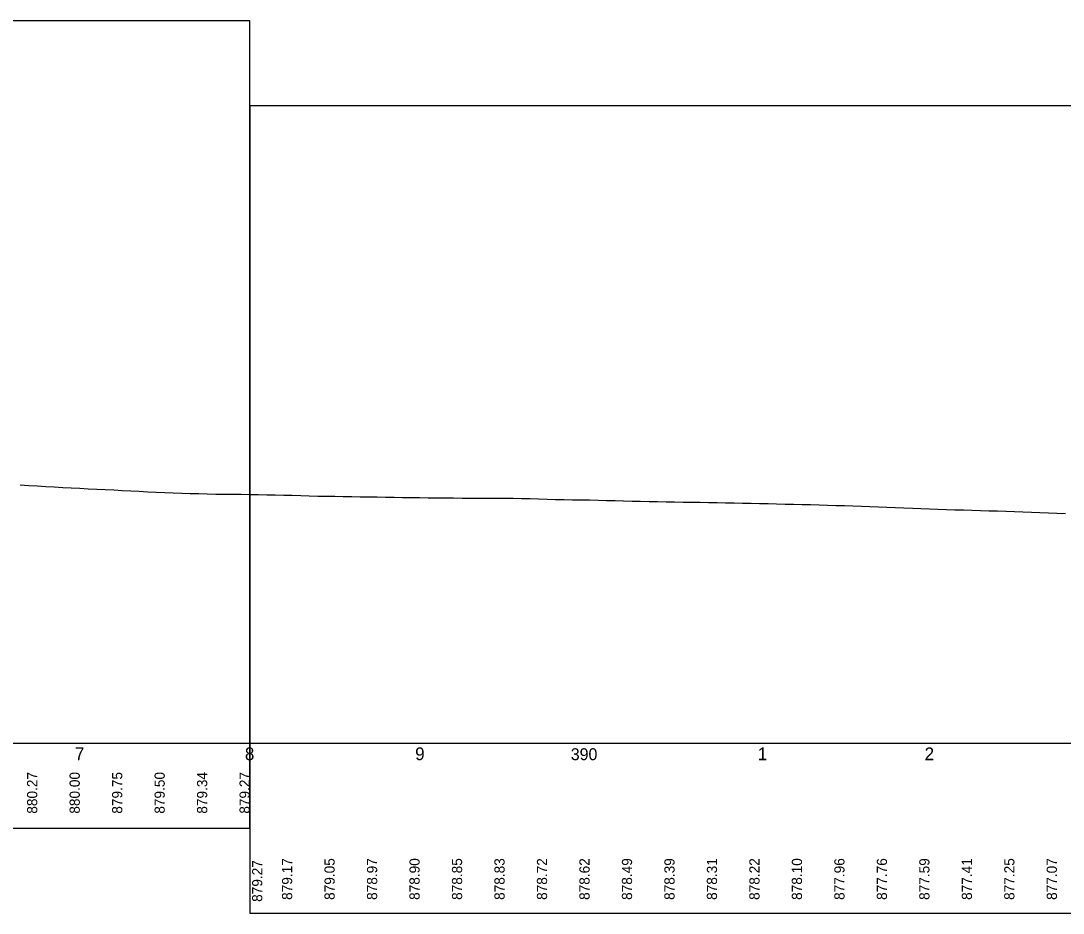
# Model space of a CAD drawing. Extents: x 4180 to 16997695, y 4 to 12629821.
# Drawn here: x 16991085 to 16991699, y 12626688 to 12627213 of the extents above; entities that cross this region are included whole.
import ezdxf

# ---------------------------------------------------------------- set-up
doc = ezdxf.new("R2010")
doc.units = 0
for name, color, linetype in [('Default', 7, 'Continuous'), ('RD_DDB_Profile_EX', 7, 'Continuous'), ('RD_DDB_StaTX', 7, 'Continuous'), ('RD_DDB_StripGrade', 7, 'Continuous'), ('RD_GPK_Profile_Cell', 7, 'Continuous')]:
    doc.layers.add(name, color=color, linetype=linetype)

msp = doc.modelspace()

# ---------------------------------------------------------------- linework, layer by layer
at = {"layer": 'Default'}
for points in [[(16989719.88, 12626737.79), (16991219.88, 12626737.79), (16991219.88, 12627212.79), (16989719.88, 12627212.79)], [(16991219.88, 12626687.79), (16992719.88, 12626687.79), (16992719.88, 12627162.79), (16991219.88, 12627162.79)]]:
    msp.add_lwpolyline(points, close=True, dxfattribs=at)
at = {"layer": 'RD_DDB_Profile_EX'}
for points in [[(16991084.88, 12626939.73), (16991089.88, 12626939.43), (16991094.88, 12626939.13), (16991099.88, 12626938.85), (16991104.88, 12626938.56), (16991109.88, 12626938.28), (16991114.88, 12626938.01), (16991119.88, 12626937.77)], [(16991119.88, 12626937.77), (16991124.88, 12626937.53), (16991129.88, 12626937.27), (16991134.88, 12626937.03), (16991139.88, 12626936.78), (16991144.88, 12626936.53), (16991149.88, 12626936.28), (16991154.88, 12626936.02), (16991159.88, 12626935.74), (16991164.88, 12626935.49), (16991169.88, 12626935.3), (16991174.88, 12626935.11), (16991179.88, 12626934.92), (16991184.88, 12626934.77), (16991189.88, 12626934.63), (16991194.88, 12626934.49), (16991199.88, 12626934.35), (16991204.88, 12626934.28), (16991209.88, 12626934.24), (16991214.88, 12626934.21), (16991219.88, 12626934.16), (16991224.88, 12626934.06), (16991229.88, 12626933.96), (16991234.88, 12626933.86), (16991239.88, 12626933.76), (16991244.88, 12626933.62), (16991249.88, 12626933.47), (16991254.88, 12626933.31), (16991259.88, 12626933.18), (16991264.88, 12626933.11), (16991269.88, 12626933.03), (16991274.88, 12626932.96), (16991279.88, 12626932.88), (16991284.88, 12626932.8), (16991289.88, 12626932.72), (16991294.88, 12626932.64), (16991299.88, 12626932.57), (16991304.88, 12626932.5), (16991309.88, 12626932.42), (16991314.88, 12626932.35), (16991319.88, 12626932.27), (16991324.88, 12626932.18), (16991329.88, 12626932.14), (16991334.88, 12626932.11), (16991339.88, 12626932.07), (16991344.88, 12626932.04), (16991349.88, 12626932.02), (16991354.88, 12626932.02), (16991359.88, 12626932.02), (16991364.88, 12626932.01), (16991369.88, 12626931.96), (16991374.88, 12626931.88), (16991379.88, 12626931.8), (16991384.88, 12626931.72), (16991389.88, 12626931.58), (16991394.88, 12626931.4), (16991399.88, 12626931.21), (16991404.88, 12626931.1), (16991409.88, 12626931.04), (16991414.88, 12626930.97), (16991419.88, 12626930.89), (16991424.88, 12626930.77), (16991429.88, 12626930.64), (16991434.88, 12626930.53), (16991439.88, 12626930.39), (16991444.88, 12626930.25), (16991449.88, 12626930.11), (16991454.88, 12626930), (16991459.88, 12626929.9), (16991464.88, 12626929.8), (16991469.88, 12626929.74), (16991474.88, 12626929.68), (16991479.88, 12626929.6), (16991484.88, 12626929.52), (16991489.88, 12626929.44), (16991494.88, 12626929.35), (16991499.88, 12626929.26), (16991504.88, 12626929.17), (16991509.88, 12626929.07), (16991514.88, 12626928.97), (16991519.88, 12626928.87), (16991524.88, 12626928.76), (16991529.88, 12626928.64), (16991534.88, 12626928.51), (16991539.88, 12626928.4), (16991544.88, 12626928.28), (16991549.88, 12626928.15), (16991554.88, 12626928.03), (16991559.88, 12626927.88), (16991564.88, 12626927.73), (16991569.88, 12626927.57), (16991574.88, 12626927.42), (16991579.88, 12626927.25), (16991584.88, 12626927.03), (16991589.88, 12626926.82), (16991594.88, 12626926.61), (16991599.88, 12626926.39), (16991604.88, 12626926.22), (16991609.88, 12626926.06), (16991614.88, 12626925.9), (16991619.88, 12626925.72)], [(16991619.88, 12626925.72), (16991624.88, 12626925.54), (16991629.88, 12626925.36), (16991634.88, 12626925.18), (16991639.88, 12626925.01), (16991644.88, 12626924.86), (16991649.88, 12626924.72), (16991654.88, 12626924.58), (16991659.88, 12626924.42), (16991664.88, 12626924.22), (16991669.88, 12626924.03), (16991674.88, 12626923.84), (16991679.88, 12626923.64), (16991684.88, 12626923.46), (16991689.88, 12626923.3), (16991694.88, 12626923.13), (16991699.88, 12626922.96)]]:
    msp.add_lwpolyline(points, dxfattribs=at)
at = {"layer": 'RD_GPK_Profile_Cell'}
msp.add_line((16972619.88, 12626787.79), (16997196.51, 12626787.79), dxfattribs=at)

# ---------------------------------------------------------------- texts
at = {"layer": 'RD_DDB_StaTX'}
for s, height, p in [('7', 7.5, (16991117, 12626777.79)), ('8', 7.5, (16991217.03, 12626777.79)), ('9', 7.5, (16991317.23, 12626777.79)), ('390', 7, (16991408.83, 12626777.79)), ('1', 7.5, (16991518.87, 12626777.79)), ('2', 7.5, (16991617.03, 12626777.79))]:
    msp.add_text(s, height=height, dxfattribs=at).set_placement(p)
at = {"layer": 'RD_DDB_StripGrade'}
for s, p in [('880.27', (16991094.88, 12626746.3)), ('880.00', (16991119.88, 12626746.3)), ('879.75', (16991144.88, 12626746.3)), ('879.50', (16991169.88, 12626746.3)), ('879.34', (16991194.88, 12626746.3)), ('879.27', (16991219.88, 12626746.3)), ('879.27', (16991227.28, 12626694.43)), ('879.17', (16991244.88, 12626695.58)), ('879.05', (16991269.88, 12626695.58)), ('878.97', (16991294.88, 12626695.58)), ('878.90', (16991319.88, 12626695.58)), ('878.85', (16991344.88, 12626695.58)), ('878.83', (16991369.88, 12626695.58)), ('878.72', (16991394.88, 12626695.58)), ('878.62', (16991419.88, 12626695.58)), ('878.49', (16991444.88, 12626695.58)), ('878.39', (16991469.88, 12626695.58)), ('878.31', (16991494.88, 12626695.58)), ('878.22', (16991519.88, 12626695.58)), ('878.10', (16991544.88, 12626695.58)), ('877.96', (16991569.88, 12626695.58)), ('877.76', (16991594.88, 12626695.58)), ('877.59', (16991619.88, 12626695.58)), ('877.41', (16991644.88, 12626695.58)), ('877.25', (16991669.88, 12626695.58)), ('877.07', (16991694.88, 12626695.58))]:
    msp.add_text(s, height=6, rotation=90, dxfattribs=at).set_placement(p)

doc.saveas('drawing.dxf')
